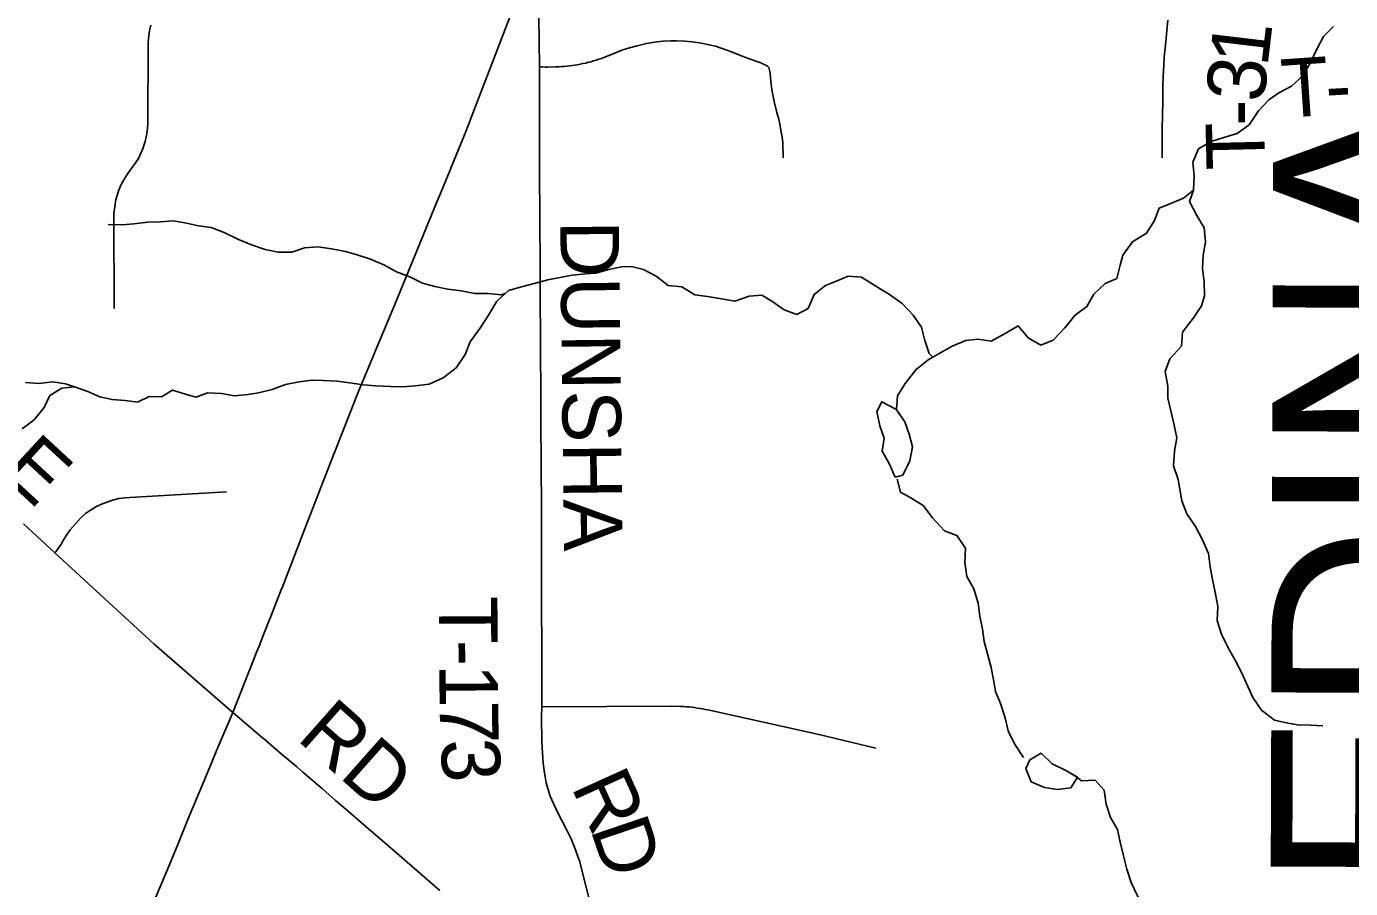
# Model space of a CAD drawing. Extents: x 0 to 34, y 0 to 22.
# Drawn here: x 6.454 to 7.738, y 14.753 to 15.589 of the extents above; entities that cross this region are included whole.
import ezdxf

# ---------------------------------------------------------------- set-up
doc = ezdxf.new("R2010")
doc.units = 0
for name, color, linetype in [('GM_X_County_Text', 7, 'Continuous'), ('GM_X_Minor_Lake', 7, 'Continuous'), ('GM_X_Minor_River', 7, 'Continuous'), ('GM_X_Township_Road', 7, 'Continuous'), ('GM_X_Township_Road_Text', 7, 'Continuous')]:
    doc.layers.add(name, color=color, linetype=linetype)

msp = doc.modelspace()

# ---------------------------------------------------------------- linework, layer by layer
at = {"layer": 'GM_X_Minor_Lake'}
for points in [[(7.2976, 15.218), (7.2966, 15.2184), (7.2836, 15.2252), (7.2787, 15.2157), (7.2818, 15.202), (7.286, 15.1898), (7.2841, 15.1773), (7.2909, 15.1655), (7.2967, 15.1522)], [(7.2977, 15.218), (7.2966, 15.2184), (7.2836, 15.2252), (7.2787, 15.2157), (7.2818, 15.202), (7.286, 15.1898), (7.2841, 15.1773), (7.2909, 15.1655), (7.2967, 15.1522)], [(7.2967, 15.1522), (7.3039, 15.1541), (7.3107, 15.1678), (7.3134, 15.1815), (7.3103, 15.1937), (7.3061, 15.2058), (7.2973, 15.2184)], [(7.2967, 15.1522), (7.3039, 15.1541), (7.3107, 15.1678), (7.3134, 15.1815), (7.3103, 15.1937), (7.3061, 15.2058), (7.2976, 15.218)], [(7.4733, 14.861), (7.4626, 14.8672), (7.4489, 14.874), (7.4382, 14.8843), (7.4272, 14.8778)], [(7.4774, 14.8577), (7.4725, 14.8615), (7.4626, 14.8672), (7.4489, 14.874), (7.4382, 14.8843), (7.4272, 14.8778)], [(7.4272, 14.8778), (7.4234, 14.8694), (7.4284, 14.8565), (7.4413, 14.8512), (7.4539, 14.8493), (7.4668, 14.8508), (7.4733, 14.861)], [(7.4272, 14.8778), (7.4234, 14.8694), (7.4284, 14.8565), (7.4413, 14.8512), (7.4539, 14.8493), (7.4668, 14.8508), (7.4736, 14.8615)]]:
    msp.add_lwpolyline(points, dxfattribs=at)
at = {"layer": 'GM_X_Minor_River'}
for points in [[(7.7218, 15.5893), (7.7119, 15.5794), (7.7051, 15.5665), (7.6994, 15.5543), (7.6922, 15.5418), (7.6808, 15.5315), (7.6686, 15.525), (7.6591, 15.5181), (7.6489, 15.5075), (7.6398, 15.4938), (7.6284, 15.4854), (7.6154, 15.4816), (7.6029, 15.4777), (7.5907, 15.4705), (7.5854, 15.4576), (7.5866, 15.4443), (7.5858, 15.4306)], [(7.5858, 15.4306), (7.5763, 15.4226), (7.5645, 15.418), (7.5527, 15.413), (7.5482, 15.4009), (7.5402, 15.3887), (7.5269, 15.3803), (7.5174, 15.3674), (7.5148, 15.3578), (7.5114, 15.3449), (7.5003, 15.3399), (7.4893, 15.3297), (7.4825, 15.3175), (7.4711, 15.3091), (7.4612, 15.2969), (7.4498, 15.2851), (7.4377, 15.2802), (7.4255, 15.2874), (7.4159, 15.2988), (7.4034, 15.2915), (7.3897, 15.2839), (7.3771, 15.2858), (7.365, 15.2846), (7.352, 15.2793), (7.3399, 15.2724), (7.3285, 15.266), (7.3167, 15.2561), (7.3064, 15.2431), (7.2988, 15.2309), (7.2977, 15.218)], [(7.5858, 15.4306), (7.582, 15.4195), (7.5893, 15.4059), (7.5962, 15.3941), (7.5977, 15.38), (7.5954, 15.3674), (7.5947, 15.3545), (7.5962, 15.3416), (7.5966, 15.3279), (7.5936, 15.3184), (7.586, 15.3066), (7.5754, 15.2929), (7.5742, 15.2792), (7.5629, 15.267), (7.5583, 15.2545), (7.561, 15.2404), (7.561, 15.2286), (7.5641, 15.2153), (7.5671, 15.2027), (7.5698, 15.1902), (7.5675, 15.1773), (7.5664, 15.1632), (7.571, 15.1499), (7.5725, 15.1404), (7.5745, 15.129), (7.5794, 15.1164), (7.5878, 15.1043), (7.5947, 15.0913), (7.6004, 15.078), (7.602, 15.0651), (7.6043, 15.053), (7.6069, 15.0404), (7.6096, 15.0267), (7.6089, 15.013), (7.6131, 14.9997), (7.6192, 14.9872), (7.6268, 14.9739), (7.6329, 14.9621), (7.6436, 14.9385), (7.652, 14.926), (7.6646, 14.9165), (7.6775, 14.9135), (7.687, 14.912), (7.6996, 14.9116), (7.7114, 14.9109)], [(6.9183, 15.3301), (6.9148, 15.329), (6.9018, 15.3301), (6.8889, 15.3301), (6.8756, 15.3327), (6.8627, 15.3346), (6.8501, 15.3369), (6.8383, 15.3403), (6.8257, 15.3463), (6.8128, 15.3513), (6.8006, 15.3581), (6.7877, 15.3634), (6.7747, 15.3676), (6.7633, 15.371), (6.75, 15.3736), (6.737, 15.3755), (6.7237, 15.3744), (6.7115, 15.3705), (6.6982, 15.3705), (6.6857, 15.3728), (6.6723, 15.3773), (6.659, 15.383), (6.6457, 15.3895), (6.6331, 15.3944), (6.621, 15.3959), (6.6092, 15.3985), (6.5966, 15.4008), (6.584, 15.3997), (6.5719, 15.3993), (6.5582, 15.3977), (6.5468, 15.397), (6.5334, 15.3973)], [(7.3331, 15.2686), (7.3296, 15.272), (7.3254, 15.2846), (7.322, 15.2975), (7.3139, 15.3093), (7.3033, 15.3207), (7.2911, 15.3294), (7.2778, 15.3374), (7.264, 15.3461), (7.2511, 15.3472), (7.2386, 15.3419), (7.2291, 15.3381), (7.218, 15.3293), (7.2123, 15.3156), (7.2013, 15.3099), (7.1888, 15.3145), (7.1769, 15.3228), (7.1674, 15.3285), (7.1549, 15.3277), (7.1412, 15.3228), (7.1282, 15.325), (7.1145, 15.3273), (7.1024, 15.3288), (7.0898, 15.3368), (7.0765, 15.3379), (7.0647, 15.347), (7.0525, 15.3535), (7.0407, 15.3565), (7.0312, 15.3561), (7.019, 15.3534), (7.0061, 15.35), (6.9966, 15.3492), (6.9832, 15.348), (6.9597, 15.3435), (6.9463, 15.34), (6.9342, 15.3366), (6.9216, 15.3331), (6.9102, 15.3229), (6.9023, 15.3092), (6.8939, 15.2962), (6.8844, 15.2833), (6.8795, 15.2711), (6.8708, 15.2582), (6.8582, 15.2483), (6.8445, 15.2422), (6.8312, 15.2406), (6.8187, 15.2398), (6.8072, 15.2402), (6.7928, 15.2406), (6.7806, 15.2417), (6.7677, 15.2436), (6.7555, 15.2451), (6.7422, 15.2458), (6.7311, 15.2462), (6.7186, 15.2447), (6.7053, 15.242), (6.6923, 15.237), (6.679, 15.234), (6.6691, 15.2324), (6.6558, 15.2309), (6.6433, 15.2332), (6.6299, 15.2339), (6.6182, 15.2297), (6.6083, 15.2327), (6.5957, 15.2365), (6.585, 15.23), (6.5729, 15.2304), (6.5618, 15.2247), (6.5497, 15.2266), (6.5371, 15.2273), (6.5253, 15.23), (6.5135, 15.2353), (6.5006, 15.2398)], [(6.5006, 15.2398), (6.4918, 15.2425), (6.4796, 15.2447), (6.4659, 15.2428), (6.453, 15.244)], [(6.5006, 15.2398), (6.4884, 15.2383), (6.4766, 15.2314), (6.4713, 15.2196), (6.4614, 15.2078), (6.45, 15.1991)], [(7.2986, 15.1503), (7.3016, 15.1374), (7.3112, 15.1324), (7.3237, 15.1245), (7.3329, 15.1127), (7.3443, 15.1002), (7.3565, 15.0956), (7.3649, 15.0831), (7.3641, 15.0694), (7.3661, 15.0557), (7.3729, 15.0439), (7.3771, 15.0298), (7.3787, 15.0173), (7.3814, 15.0048), (7.3829, 14.9926), (7.3863, 14.9793), (7.3898, 14.9675), (7.3921, 14.9538), (7.394, 14.9443), (7.3986, 14.9325), (7.4032, 14.9188), (7.4062, 14.9059), (7.4123, 14.8934), (7.4211, 14.8801)], [(7.5591, 14.7137), (7.5469, 14.7216), (7.5374, 14.733), (7.5316, 14.746), (7.5255, 14.7589), (7.5213, 14.7718), (7.5179, 14.7847), (7.5148, 14.798), (7.5121, 14.8102), (7.5053, 14.822), (7.5011, 14.8349), (7.4992, 14.8486), (7.4904, 14.8581), (7.4774, 14.8577)]]:
    msp.add_lwpolyline(points, dxfattribs=at)
at = {"layer": 'GM_X_Township_Road'}
for points in [[(6.774, 15.2302), (6.7766, 15.2367), (6.7977, 15.2874), (6.8113, 15.3196), (6.8525, 15.4198), (6.8554, 15.4267), (6.8647, 15.4493), (6.8657, 15.4517), (6.8781, 15.4825), (6.8843, 15.498), (6.8845, 15.4983), (6.9326, 15.6239), (6.9339, 15.6272), (6.946, 15.66), (6.9481, 15.6667), (6.9493, 15.672), (6.9504, 15.6782), (6.951, 15.6849), (6.9511, 15.6899), (6.9505, 15.8976)], [(6.9523, 15.3566), (6.952, 15.4023), (6.9517, 15.4498), (6.9517, 15.5502), (6.951, 15.5991), (6.9505, 15.6039), (6.9497, 15.6075)], [(6.539, 15.3157), (6.5387, 15.4042), (6.5389, 15.408), (6.5393, 15.4123), (6.54, 15.4169), (6.5408, 15.4215), (6.5419, 15.4252), (6.5431, 15.4288), (6.5457, 15.4352), (6.5472, 15.4383), (6.5488, 15.4411), (6.5523, 15.4465), (6.5598, 15.4571), (6.5626, 15.4613), (6.5653, 15.4669), (6.5672, 15.4716), (6.5682, 15.4747), (6.569, 15.4776), (6.5701, 15.4821), (6.5711, 15.4871), (6.5715, 15.4908), (6.5717, 15.4946), (6.5722, 15.573), (6.5725, 15.5776), (6.5734, 15.5849), (6.5745, 15.5906)], [(7.5554, 15.4617), (7.5556, 15.4896), (7.5559, 15.5034), (7.5561, 15.5163), (7.5563, 15.53), (7.5565, 15.5415), (7.5571, 15.5513), (7.5576, 15.5599), (7.5583, 15.5682), (7.559, 15.5745), (7.5599, 15.5853), (7.5609, 15.5953)], [(6.9517, 15.5502), (6.9543, 15.5501), (6.957, 15.5499), (6.9596, 15.5499), (6.9676, 15.55), (6.9702, 15.5501), (6.9729, 15.5503), (6.9755, 15.5505), (6.9781, 15.5507), (6.9808, 15.551), (6.9834, 15.5514), (6.986, 15.5518), (6.9886, 15.5522), (6.9912, 15.5527), (6.9938, 15.5532), (6.9964, 15.5538), (6.999, 15.5545), (7.0015, 15.5551), (7.0041, 15.5558), (7.0066, 15.5566), (7.0091, 15.5574), (7.0116, 15.5582), (7.0141, 15.5591), (7.0166, 15.5601), (7.0324, 15.5665), (7.0388, 15.5685), (7.0464, 15.5706), (7.0554, 15.5727), (7.0633, 15.574), (7.0711, 15.5749), (7.0791, 15.5753), (7.0844, 15.5752), (7.0925, 15.5749), (7.0996, 15.5742), (7.1067, 15.5734), (7.1162, 15.5716), (7.1223, 15.57), (7.1288, 15.568), (7.1377, 15.5645), (7.1481, 15.5604), (7.1624, 15.5553), (7.1662, 15.554), (7.1689, 15.5528), (7.1719, 15.5513), (7.173, 15.5505), (7.1739, 15.5494)], [(7.1878, 15.4618), (7.1875, 15.4764), (7.187, 15.4819), (7.1864, 15.4851), (7.1839, 15.4979), (7.1818, 15.5059), (7.1792, 15.5165), (7.1778, 15.5228), (7.1769, 15.5282), (7.1762, 15.5334), (7.1757, 15.5396), (7.1752, 15.5439), (7.1747, 15.5469), (7.1739, 15.5494)], [(6.9531, 15.1723), (6.953, 15.1982), (6.9529, 15.2315), (6.9526, 15.2768), (6.9524, 15.3357), (6.9523, 15.3566)], [(6.6543, 14.9239), (6.6776, 14.983), (6.6806, 14.9906), (6.6808, 14.991), (6.6898, 15.0139), (6.691, 15.0171), (6.7015, 15.0437), (6.702, 15.0449), (6.7228, 15.0987), (6.7487, 15.1652), (6.774, 15.2302)], [(6.9997, 14.7432), (6.9941, 14.7659), (6.9907, 14.7791), (6.9886, 14.7853), (6.9857, 14.7931), (6.9824, 14.8014), (6.9777, 14.8104), (6.9689, 14.8279), (6.962, 14.8428), (6.9597, 14.85), (6.9582, 14.8557), (6.957, 14.8616), (6.9561, 14.8676), (6.9553, 14.8748), (6.9544, 14.8848), (6.9539, 14.895), (6.9536, 14.9197), (6.9539, 14.9294), (6.9538, 14.9613), (6.9539, 14.9777), (6.9539, 14.9928), (6.9537, 15.0214), (6.9536, 15.0547), (6.9535, 15.0879), (6.9537, 15.1213), (6.9531, 15.1653), (6.9531, 15.1723)], [(6.4815, 15.0788), (6.4824, 15.0798), (6.4876, 15.0872), (6.4896, 15.0906), (6.4929, 15.0958), (6.4964, 15.101), (6.5015, 15.107), (6.5067, 15.1125), (6.5114, 15.1168), (6.516, 15.12), (6.5219, 15.1235), (6.5267, 15.1259), (6.5328, 15.1282), (6.5375, 15.1297), (6.5437, 15.1313), (6.5491, 15.1321), (6.5542, 15.1325), (6.6479, 15.1379)], [(6.8551, 14.7512), (6.8502, 14.7554), (6.8062, 14.7934), (6.7787, 14.8172), (6.7661, 14.8281), (6.7539, 14.8386), (6.741, 14.8498), (6.7221, 14.8661), (6.7158, 14.8714), (6.7012, 14.8839), (6.6837, 14.8988), (6.6831, 14.8993), (6.6543, 14.9239), (6.5779, 14.99), (6.4815, 15.0788), (6.4512, 15.1068)], [(6.4954, 14.541), (6.5052, 14.5647), (6.5104, 14.5775), (6.5166, 14.5927), (6.5226, 14.6075), (6.537, 14.6426), (6.5506, 14.6761), (6.5553, 14.6876), (6.5687, 14.7191), (6.5801, 14.7463), (6.5924, 14.7756), (6.6014, 14.7973), (6.6105, 14.8201), (6.63, 14.8663), (6.6397, 14.89), (6.6543, 14.9239)], [(6.9539, 14.9294), (7.0798, 14.9299), (7.0887, 14.9298), (7.0913, 14.9296), (7.094, 14.9294), (7.0966, 14.9292), (7.0992, 14.9289), (7.1019, 14.9286), (7.1045, 14.9282), (7.1071, 14.9278), (7.1097, 14.9273), (7.1123, 14.9268), (7.1149, 14.9263), (7.2213, 14.9027), (7.2777, 14.8894)]]:
    msp.add_lwpolyline(points, dxfattribs=at)

# ---------------------------------------------------------------- texts
at = {"layer": 'GM_X_County_Text'}
msp.add_text('MEDINA COUNTY', height=0.189394, rotation=89.8023, dxfattribs=at).set_placement((7.8494, 14.542))
at = {"layer": 'GM_X_Township_Road_Text'}
for s, height, rotation, p in [('1', 0.0568, 83.1926, (7.6576, 15.5493)), ('3', 0.0568, 85.0449, (7.6546, 15.5149)), ('T', 0.0568, 3.9543, (7.6729, 15.5005)), ('CODDINGVILLE', 0.056818, 317.2645, (6.0487, 15.5053)), ('-', 0.0568, 3.2647, (7.7151, 15.5034)), ('-', 0.0568, 89.2349, (7.6544, 15.4927)), ('T', 0.0568, 91.3759, (7.6554, 15.4508)), ('DUNSHA', 0.05682, 270.6577, (6.9717, 15.4008)), ('T', 0.0568, 270.3429, (6.854, 15.0366)), ('-', 0.0568, 270.3723, (6.8543, 14.9941)), ('1', 0.0568, 270.4789, (6.8544, 14.9707)), ('RD', 0.05682, 318.4888, (6.715, 14.8981)), ('7', 0.0568, 270.8628, (6.8547, 14.9353)), ('3', 0.0568, 273.9439, (6.8554, 14.8969)), ('R', 0.0568, 294.4036, (6.9819, 14.8521)), ('D', 0.0568, 288.7817, (7.0006, 14.811))]:
    msp.add_text(s, height=height, rotation=rotation, dxfattribs=at).set_placement(p)

doc.saveas('drawing.dxf')
